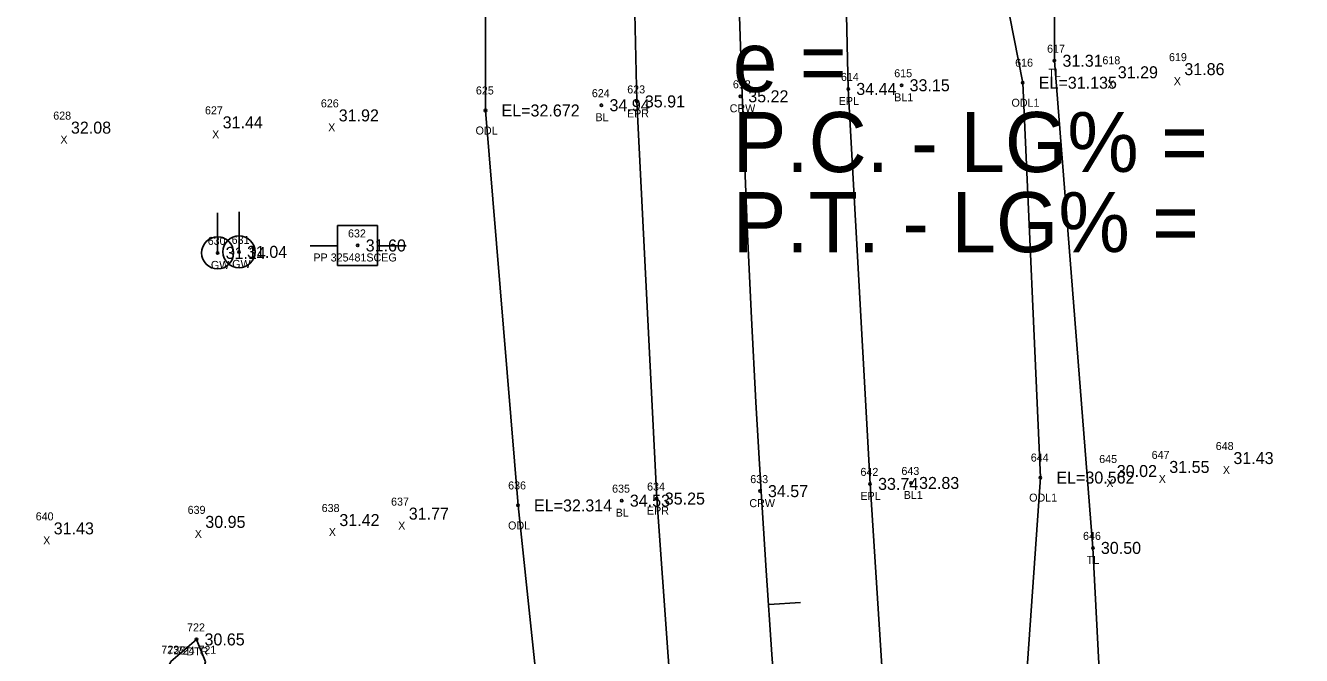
# Model space of a CAD drawing. Extents: x 2042117 to 2045853, y 303080 to 309569.
# Drawn here: x 2042751.6 to 2042911.1, y 307210.7 to 307289.3 of the extents above; entities that cross this region are included whole.
import ezdxf

# ---------------------------------------------------------------- set-up
doc = ezdxf.new("R2010")
doc.units = 0
for name, color, linetype in [('RD_DTM_BkLn_txCode', 7, 'Continuous'), ('RD_EX_H2O', 7, 'Continuous'), ('RD_EX_H2O_txCode', 7, 'Continuous'), ('RD_EX_Misc_txCode', 7, 'Continuous'), ('RD_EX_Road', 7, 'Continuous'), ('RD_EX_Road_txCode', 7, 'Continuous'), ('RD_EX_TX_H2O_ELEV', 7, 'Continuous'), ('RD_EX_TX_Misc_ELEV', 7, 'Continuous'), ('RD_EX_TX_Road_ELEV', 7, 'Continuous'), ('RD_EX_TX_UT_ELEV', 7, 'Continuous'), ('RD_EX_TX_VEG_ELEV', 7, 'Continuous'), ('RD_EX_UT', 7, 'Continuous'), ('RD_EX_UT_txCode', 7, 'Continuous'), ('RD_EX_VEG', 7, 'Continuous'), ('RD_EX_VEG_txCode', 7, 'Continuous'), ('RD_HC_Cl', 7, 'Continuous'), ('RD_HC_Data', 7, 'Continuous'), ('RD_HC_Data_Tic', 7, 'Continuous'), ('RD_HC_Survey_ELEV', 7, 'Continuous'), ('RD_HC_Survey_txCode', 7, 'Continuous'), ('RD_SMD_Locator', 7, 'Continuous')]:
    doc.layers.add(name, color=color, linetype=linetype)

msp = doc.modelspace()

# ---------------------------------------------------------------- linework, layer by layer
at = {"layer": 'RD_EX_H2O'}
for points in [[(2042865.43, 307427.05), (2042866.84, 307378.87), (2042866.82, 307329.93), (2042876.23, 307282.16), (2042878.43, 307232.86), (2042875.08, 307184.77), (2042887.19, 307136.65), (2042884.32, 307120.02), (2042882.74, 307087.49), (2042892.51, 307039.16), (2042896.41, 306990.42), (2042899.37, 306973.37), (2042910.05, 306942.23), (2042920.75, 306896.67), (2042927.15, 306846.78), (2042945.6, 306801.59), (2042960.32, 306754.61), (2042976.65, 306708.74), (2042994.63, 306662.76), (2043013.3, 306616.98), (2043029.17, 306571.91), (2043050.77, 306528.53)], [(2042809.03, 307329.14), (2042809.1, 307278.69), (2042813.16, 307229.38), (2042818.57, 307178.31), (2042821.22, 307157.54)], [(2042814.03, 307149.05), (2042812.35, 307160.17), (2042807.99, 307165.58), (2042796.92, 307172.8), (2042790.51, 307171.69), (2042792.71, 307164.76), (2042799.25, 307156.93), (2042800.45, 307151.16), (2042798.47, 307149.32), (2042796.14, 307150.22), (2042774.77, 307172.67), (2042769.03, 307177.06), (2042766.93, 307183.71), (2042770.19, 307195.04), (2042774.13, 307209.86), (2042772.99, 307212.66), (2042769.77, 307209.88), (2042763.43, 307196.28), (2042761.19, 307187.09), (2042759.15, 307187.36), (2042738.04, 307209.09), (2042720.64, 307223.82), (2042688.55, 307257.73)]]:
    msp.add_lwpolyline(points, dxfattribs=at)
at = {"layer": 'RD_EX_Road'}
for points in [[(2042828.36, 307428.87), (2042826.99, 307378.91), (2042826.88, 307329.29), (2042828.01, 307279.82), (2042830.5, 307230.24), (2042834.09, 307180.37), (2042835.89, 307157.73), (2042833.55, 307154.38), (2042836.54, 307132.83), (2042837.33, 307130.11), (2042837.64, 307128.77), (2042839.22, 307126.16), (2042844.98, 307081.33), (2042852.86, 307032.13), (2042861.74, 306982.99), (2042871.66, 306934.62), (2042883.38, 306885.88), (2042895.94, 306837.56), (2042909.76, 306789.89)], [(2042855.03, 307427.78), (2042853.64, 307379.19), (2042853.31, 307329.44), (2042854.43, 307281.38), (2042857.15, 307232.07), (2042860.27, 307183.35), (2042865.16, 307133.89), (2042871.37, 307085.7), (2042878.53, 307037.13), (2042886.97, 306988.21), (2042897.02, 306940.01), (2042908.28, 306892.66), (2042921.09, 306844.85), (2042934.41, 306798.2)]]:
    msp.add_lwpolyline(points, dxfattribs=at)
at = {"layer": 'RD_EX_UT'}
for p, q in [((2042775.63, 307260.91), (2042775.63, 307265.91)), ((2042778.3, 307261.04), (2042778.3, 307266.04)), ((2042795.62, 307264.35), (2042790.62, 307264.35)), ((2042790.62, 307264.35), (2042790.62, 307259.35)), ((2042795.62, 307259.35), (2042795.62, 307264.35)), ((2042787.19, 307261.79), (2042790.66, 307261.79)), ((2042795.55, 307261.79), (2042799.19, 307261.79)), ((2042790.62, 307259.35), (2042795.62, 307259.35))]:
    msp.add_line(p, q, dxfattribs=at)
for centre in [(2042775.63, 307260.91), (2042778.3, 307261.04)]:
    msp.add_circle(centre, 2, dxfattribs=at)
at = {"layer": 'RD_EX_VEG'}
msp.add_lwpolyline([(2042885.61, 307482.85), (2042881.1, 307379.92), (2042880.44, 307351.7), (2042880.19, 307284.9), (2042884.99, 307224.08), (2042886.48, 307195.22), (2042890.83, 307127.55), (2042909.45, 307007.86), (2042916.1, 306960.95), (2042918.56, 306940.03), (2042926.66, 306909), (2042942.91, 306849.91), (2042954.33, 306802.72), (2042963.56, 306806.84), (2042974.33, 306847.25), (2043002.07, 306860.54), (2043032.14, 306846.51)], dxfattribs=at)
at = {"layer": 'RD_HC_Cl'}
msp.add_arc((2044751.25, 307348.43), 1911.29, 137.68184, 219.86836, dxfattribs=at)
at = {"layer": 'RD_HC_Data_Tic'}
msp.add_line((2042844.48, 307217), (2042848.47, 307217.27), dxfattribs=at)
at = {"layer": 'RD_SMD_Locator'}
for centre in [(2042880.19, 307284.9), (2042854.43, 307281.38), (2042861.09, 307281.84), (2042876.23, 307282.16), (2042823.59, 307279.35), (2042828.01, 307279.82), (2042840.93, 307280.46), (2042809.1, 307278.69), (2042793.13, 307261.84), (2042775.63, 307260.91), (2042778.3, 307261.04), (2042857.15, 307232.07), (2042862.27, 307232.19), (2042878.43, 307232.86), (2042826.13, 307229.98), (2042830.5, 307230.24), (2042843.39, 307231.17), (2042813.16, 307229.38), (2042884.99, 307224.08), (2042772.99, 307212.66)]:
    msp.add_circle(centre, 0.15, dxfattribs=at)

# ---------------------------------------------------------------- texts
at = {"layer": 'RD_DTM_BkLn_txCode'}
for s, p in [('615', (2042860.17, 307282.84)), ('624', (2042822.39, 307280.35)), ('BL1', (2042860.17, 307279.84)), ('BL', (2042822.84, 307277.35)), ('643', (2042861.07, 307233.19)), ('635', (2042824.92, 307230.98)), ('BL1', (2042861.35, 307230.19)), ('BL', (2042825.37, 307227.98))]:
    msp.add_text(s, height=1, dxfattribs=at).set_placement(p)
at = {"layer": 'RD_EX_H2O_txCode'}
for s, p in [('616', (2042875.28, 307284.16)), ('625', (2042807.9, 307280.69)), ('ODL1', (2042874.82, 307279.16)), ('ODL', (2042807.86, 307275.69)), ('644', (2042877.23, 307234.86)), ('636', (2042811.93, 307231.38)), ('ODL1', (2042877.03, 307229.86)), ('ODL', (2042811.92, 307226.38)), ('722', (2042771.81, 307213.66)), ('723', (2042768.59, 307210.88)), ('725', (2042769.36, 307210.78)), ('724', (2042770.52, 307210.76)), ('DTR', (2042771.72, 307210.66)), ('721', (2042773.23, 307210.86))]:
    msp.add_text(s, height=1, dxfattribs=at).set_placement(p)
at = {"layer": 'RD_EX_Misc_txCode'}
for s, p in [('619', (2042894.5, 307284.85)), ('618', (2042886.18, 307284.46)), ('X', (2042895.1, 307281.85)), ('X', (2042886.79, 307281.46)), ('626', (2042788.53, 307279.08)), ('628', (2042755.09, 307277.55)), ('627', (2042774.05, 307278.21)), ('X', (2042789.44, 307276.08)), ('X', (2042755.98, 307274.55)), ('X', (2042774.94, 307275.21)), ('648', (2042900.34, 307236.3)), ('645', (2042885.78, 307234.68)), ('647', (2042892.33, 307235.19)), ('X', (2042901.23, 307233.3)), ('X', (2042886.67, 307231.68)), ('X', (2042893.22, 307232.19)), ('637', (2042797.3, 307229.36)), ('640', (2042752.9, 307227.52)), ('639', (2042771.88, 307228.33)), ('638', (2042788.63, 307228.56)), ('X', (2042798.19, 307226.36)), ('X', (2042753.83, 307224.52)), ('X', (2042772.77, 307225.33)), ('X', (2042789.52, 307225.56))]:
    msp.add_text(s, height=1, dxfattribs=at).set_placement(p)
at = {"layer": 'RD_EX_Road_txCode'}
for s, p in [('614', (2042853.51, 307282.38)), ('623', (2042826.81, 307280.82)), ('EPL', (2042853.23, 307279.38)), ('EPR', (2042826.78, 307277.82)), ('642', (2042855.95, 307233.07)), ('634', (2042829.29, 307231.24)), ('EPL', (2042855.95, 307230.07)), ('EPR', (2042829.27, 307228.24))]:
    msp.add_text(s, height=1, dxfattribs=at).set_placement(p)
at = {"layer": 'RD_EX_TX_H2O_ELEV'}
for s, p in [('EL=31.135', (2042878.23, 307281.41)), ('EL=32.672', (2042811.1, 307277.94)), ('EL=30.562', (2042880.43, 307232.11)), ('EL=32.314', (2042815.16, 307228.63)), ('30.65', (2042773.99, 307211.91))]:
    msp.add_text(s, height=1.5, dxfattribs=at).set_placement(p)
at = {"layer": 'RD_EX_TX_Misc_ELEV'}
for s, p in [('31.86', (2042896.42, 307283.1)), ('31.29', (2042888.1, 307282.71)), ('33.15', (2042862.09, 307281.09)), ('34.94', (2042824.59, 307278.6)), ('31.44', (2042776.26, 307276.46)), ('31.92', (2042790.76, 307277.33)), ('32.08', (2042757.3, 307275.8)), ('31.55', (2042894.54, 307233.44)), ('31.43', (2042902.55, 307234.55)), ('30.02', (2042887.98, 307232.93)), ('32.83', (2042863.27, 307231.44)), ('34.53', (2042827.13, 307229.23)), ('31.77', (2042799.51, 307227.61)), ('31.43', (2042755.15, 307225.77)), ('30.95', (2042774.09, 307226.58)), ('31.42', (2042790.84, 307226.81))]:
    msp.add_text(s, height=1.5, dxfattribs=at).set_placement(p)
at = {"layer": 'RD_EX_TX_Road_ELEV'}
for s, p in [('34.44', (2042855.43, 307280.63)), ('35.91', (2042829.01, 307279.07)), ('33.74', (2042858.15, 307231.32)), ('35.25', (2042831.5, 307229.49))]:
    msp.add_text(s, height=1.5, dxfattribs=at).set_placement(p)
at = {"layer": 'RD_EX_TX_UT_ELEV'}
for s, p in [('31.14', (2042776.63, 307260.16)), ('31.04', (2042779.3, 307260.29))]:
    msp.add_text(s, height=1.5, dxfattribs=at).set_placement(p)
at = {"layer": 'RD_EX_TX_VEG_ELEV'}
for s, p in [('31.31', (2042881.19, 307284.15)), ('30.50', (2042885.99, 307223.33))]:
    msp.add_text(s, height=1.5, dxfattribs=at).set_placement(p)
at = {"layer": 'RD_EX_UT_txCode'}
for s, p in [('632', (2042791.92, 307262.84)), ('630', (2042774.39, 307261.91)), ('631', (2042777.38, 307262.04)), ('PP 325481SCEG', (2042787.6, 307259.84)), ('GW', (2042774.79, 307258.91)), ('GW', (2042777.45, 307259.04))]:
    msp.add_text(s, height=1, dxfattribs=at).set_placement(p)
at = {"layer": 'RD_EX_VEG_txCode'}
for s, p in [('617', (2042879.27, 307285.9)), ('TL', (2042879.42, 307282.9)), ('646', (2042883.76, 307225.08)), ('TL', (2042884.22, 307222.08))]:
    msp.add_text(s, height=1, dxfattribs=at).set_placement(p)
at = {"layer": 'RD_HC_Data'}
for s, p in [('e = ', (2042840, 307281)), ('P.C. - LG% = ', (2042840, 307271)), ('P.T. - LG% = ', (2042840, 307261))]:
    msp.add_text(s, height=7.5, dxfattribs=at).set_placement(p)
at = {"layer": 'RD_HC_Survey_ELEV'}
for s, p in [('35.22', (2042841.93, 307279.71)), ('31.60', (2042794.13, 307261.09)), ('34.57', (2042844.39, 307230.42))]:
    msp.add_text(s, height=1.5, dxfattribs=at).set_placement(p)
at = {"layer": 'RD_HC_Survey_txCode'}
for s, p in [('613', (2042840.01, 307281.46)), ('CRW', (2042839.61, 307278.46)), ('633', (2042842.18, 307232.17)), ('CRW', (2042842.07, 307229.17))]:
    msp.add_text(s, height=1, dxfattribs=at).set_placement(p)

doc.saveas('drawing.dxf')
